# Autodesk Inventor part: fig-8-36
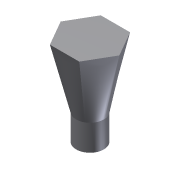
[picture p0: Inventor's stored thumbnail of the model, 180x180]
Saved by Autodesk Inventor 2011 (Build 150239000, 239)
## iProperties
Created: 2004-05
Part Number: fig-8-36
Document SubType Name: Modeling
Designer: CADCIM Technologies
Manufacturer: Standard
Standards Organization: Custom
Density: 1 g/cm^3
Author: CADCIM Technologies
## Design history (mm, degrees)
sketch "Sketch1"
  geometry: C1 r 16.344 at (0, 0)
  constraints: 1 centre point
extrude "Extrusion1" new body sketch "Sketch1" distance "d0" = 30.75; taper "d1" = 0 deg
workplane "Work Plane1"
sketch "Sketch2"
  geometry: L1 (34.788, 0)-(17.394, -30.128); L2 (17.394, -30.128)-(-17.394, -30.128); L3 (-17.394, -30.128)-(-34.788, 0); L4 (-34.788, 0)-(-17.394, 30.128); L5 (-17.394, 30.128)-(17.394, 30.128); L6 (17.394, 30.128)-(34.788, 0); 2 further points
  constraints: 12 end point, 1 coincident, 12 other
loft "Loft2" sketch "Sketch2" dims "d7" = 0, "d8" = 90 deg, "d9" = 0, "d10" = 90 deg
  node "Edges2"
body "Solid1"
other parameters: "d2" = 75
